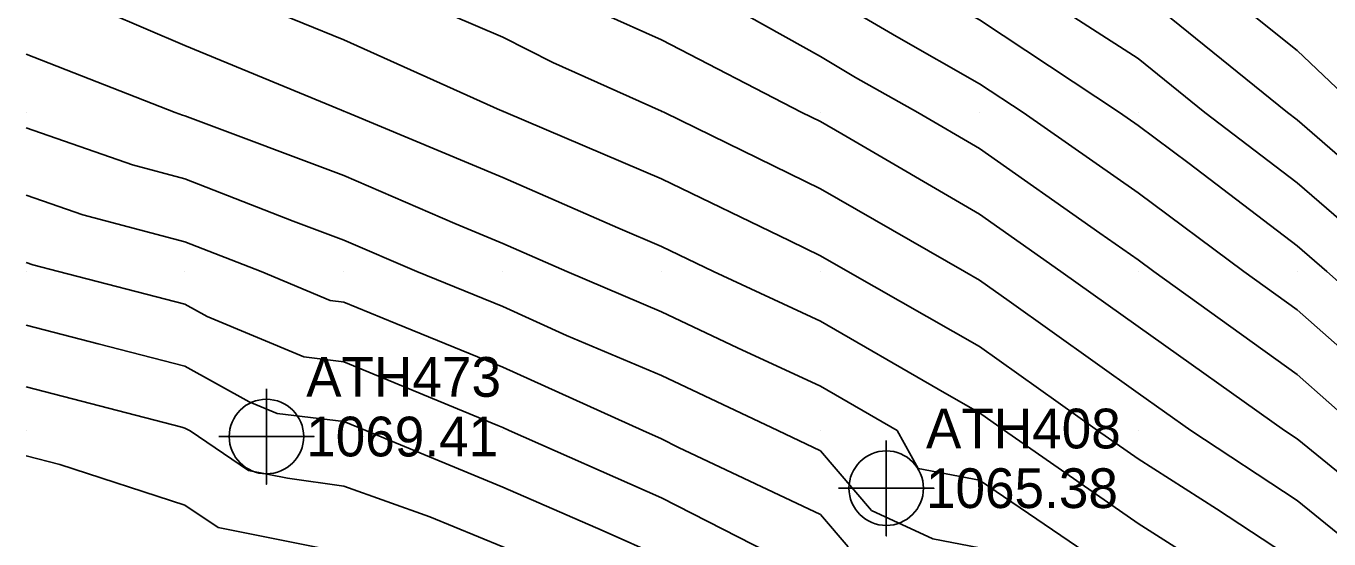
# Model space of a CAD drawing. Extents: x 1213164 to 1213550, y 766120 to 766870.
# Drawn here: x 1213170 to 1213252, y 766303.2 to 766335.4 of the extents above; entities that cross this region are included whole.
import ezdxf

# ---------------------------------------------------------------- set-up
doc = ezdxf.new("R2010")
doc.units = 0
for name, color, linetype in [('Default', 7, 'Continuous'), ('Exist DTM QL2 LIDAR Elevation Point', 7, 'Continuous'), ('Exist DTM Regular Point CELL', 7, 'Continuous'), ('Exist DTM Regular Point Cogo Elevation', 7, 'Continuous'), ('Exist DTM Regular Point Cogo Number', 7, 'Continuous')]:
    doc.layers.add(name, color=color, linetype=linetype)

msp = doc.modelspace()

# ---------------------------------------------------------------- linework, layer by layer
at = {"layer": 'Default'}
for points in [[(1213254.11, 766330), (1213250, 766333.906), (1213242.397, 766340), (1213240, 766341.58), (1213235.649, 766344.351), (1213230, 766347.761), (1213225.936, 766350), (1213220, 766353.174), (1213213.578, 766356.422), (1213210, 766358.269), (1213208.856, 766358.856), (1213206.616, 766360), (1213200, 766363.217), (1213193.598, 766366.402), (1213190, 766368.183), (1213182.11, 766370), (1213180, 766370.389), (1213179.565, 766370.435), (1213170, 766371.892)], [(1213280, 766300.545), (1213270.63, 766310), (1213270, 766310.688), (1213260.995, 766320), (1213260, 766320.923), (1213253.326, 766326.674), (1213250, 766329.544), (1213249.402, 766330), (1213240, 766337.619), (1213236.293, 766340), (1213230, 766343.799), (1213221.541, 766348.459), (1213220, 766349.323), (1213218.726, 766350), (1213210, 766354.505), (1213206.367, 766356.367), (1213200, 766359.619), (1213199.265, 766360), (1213190, 766364.587), (1213184.041, 766365.959), (1213180, 766367.027), (1213171.308, 766368.692), (1213170, 766368.959)], [(1213276.631, 766300), (1213270, 766306.688), (1213266.673, 766310), (1213260, 766316.88), (1213256.467, 766320), (1213250, 766325.581), (1213244.199, 766330), (1213240, 766333.403), (1213230.486, 766339.514), (1213230, 766339.835), (1213229.895, 766339.895), (1213229.716, 766340), (1213220, 766345.451), (1213211.434, 766350), (1213210, 766350.74), (1213203.878, 766353.878), (1213200, 766355.859), (1213191.999, 766360), (1213190, 766360.99), (1213188.714, 766361.286), (1213180, 766363.589), (1213175.561, 766364.439), (1213170, 766365.577)], [(1213270, 766302.77), (1213262.739, 766310), (1213260, 766312.824), (1213251.874, 766320), (1213250, 766321.617), (1213243.209, 766326.791), (1213240, 766329.186), (1213238.829, 766330), (1213230, 766335.826), (1213227.335, 766337.335), (1213222.813, 766340), (1213220, 766341.578), (1213216.634, 766343.366), (1213210, 766346.896), (1213204.099, 766350), (1213201.389, 766351.389), (1213200, 766352.098), (1213195.651, 766354.349), (1213190, 766356.816), (1213180.571, 766360), (1213180, 766360.151), (1213179.813, 766360.187), (1213170, 766362.194)], [(1213268.891, 766300), (1213260, 766308.854), (1213258.598, 766310), (1213250, 766317.59), (1213246.649, 766320), (1213240, 766324.962), (1213232.752, 766330), (1213230, 766331.816), (1213224.775, 766334.775), (1213220, 766337.59), (1213215.698, 766340), (1213210, 766343.032), (1213203.604, 766346.396), (1213200, 766348.087), (1213195.55, 766350), (1213190, 766352.422), (1213186.342, 766353.658), (1213180, 766356.001), (1213171.968, 766358.032), (1213170, 766358.69)], [(1213265.104, 766300), (1213260, 766305.082), (1213253.986, 766310), (1213250, 766313.518), (1213240.988, 766320), (1213240, 766320.738), (1213237.58, 766322.42), (1213230, 766327.738), (1213226.127, 766330), (1213222.215, 766332.215), (1213220, 766333.521), (1213211.993, 766338.007), (1213210, 766339.037), (1213209.334, 766339.334), (1213208.013, 766340), (1213200, 766343.759), (1213193.406, 766346.594), (1213190, 766347.998), (1213184.923, 766350), (1213180, 766351.819), (1213177.565, 766352.435), (1213170, 766354.961)], [(1213260, 766301.311), (1213252.811, 766307.189), (1213250, 766309.475), (1213249.199, 766310), (1213240, 766316.542), (1213235.135, 766320), (1213230, 766323.602), (1213221.338, 766328.662), (1213220, 766329.432), (1213218.836, 766330), (1213210, 766334.564), (1213206.242, 766336.242), (1213200, 766339.388), (1213198.575, 766340), (1213190, 766343.534), (1213184.165, 766345.835), (1213180, 766347.509), (1213173.693, 766350), (1213170, 766351.233)], [(1213256.902, 766300), (1213250, 766305.613), (1213243.308, 766310), (1213240, 766312.352), (1213231.867, 766318.133), (1213230, 766319.462), (1213229.055, 766320), (1213220, 766325.211), (1213210.178, 766330), (1213210, 766330.092), (1213203.15, 766333.15), (1213200, 766334.738), (1213191.698, 766338.302), (1213190, 766339.065), (1213187.713, 766340), (1213180, 766343.099), (1213174.877, 766345.123), (1213170, 766347.129)], [(1213250, 766301.751), (1213244.916, 766305.084), (1213240, 766308.217), (1213237.431, 766310), (1213230, 766315.291), (1213221.721, 766320), (1213220, 766320.99), (1213218.068, 766321.932), (1213210, 766325.834), (1213200.188, 766330), (1213200.058, 766330.058), (1213200, 766330.087), (1213199.847, 766330.153), (1213190, 766334.579), (1213182.255, 766337.745), (1213180, 766338.678), (1213176.902, 766340), (1213170, 766342.839)], [(1213246.514, 766300), (1213240, 766304.152), (1213231.573, 766310), (1213230, 766311.12), (1213227.402, 766312.598), (1213220, 766316.876), (1213213.267, 766320), (1213210, 766321.58), (1213207.254, 766322.746), (1213200, 766325.921), (1213190.206, 766330), (1213190, 766330.092), (1213189.844, 766330.156), (1213180, 766334.227), (1213172.625, 766337.375), (1213170, 766338.401)], [(1213239.716, 766300.284), (1213230, 766306.889), (1213226.146, 766307.619), (1213224.835, 766310), (1213220, 766312.795), (1213214.786, 766315.214), (1213210, 766317.474), (1213204.028, 766320), (1213200, 766321.763), (1213196.979, 766323.021), (1213190, 766326.033), (1213180.326, 766329.674), (1213180, 766329.801), (1213179.842, 766329.842), (1213179.392, 766330), (1213170, 766333.67)], [(1213230, 766302.636), (1213227.067, 766303.191), (1213223.222, 766304.966), (1213220, 766308.734), (1213217.318, 766310), (1213210, 766313.457), (1213204.01, 766315.99), (1213200, 766317.806), (1213194.593, 766320), (1213190, 766321.982), (1213186.822, 766323.178), (1213180, 766325.836), (1213176.703, 766326.703), (1213170, 766329.05)], [(1213221.741, 766302.684), (1213220, 766304.721), (1213211.062, 766308.938), (1213210, 766309.482), (1213208.825, 766310), (1213200, 766313.997), (1213193.273, 766316.727), (1213190, 766318.082), (1213189.148, 766318.184), (1213184.802, 766320), (1213180, 766321.87), (1213173.564, 766323.564), (1213170, 766324.812)], [(1213218.661, 766301.339), (1213210, 766305.771), (1213200.416, 766310), (1213200, 766310.189), (1213199.683, 766310.317), (1213190, 766314.326), (1213187.478, 766314.628), (1213181.4, 766317.168), (1213180, 766317.942), (1213172.04, 766320), (1213170.425, 766320.425), (1213170, 766320.574)], [(1213246.98, 766280), (1213240, 766284.817), (1213231.271, 766290), (1213230, 766290.761), (1213228.077, 766291.923), (1213220, 766296.782), (1213214.026, 766300), (1213210, 766302.06), (1213206.313, 766303.687), (1213200, 766306.436), (1213191.376, 766310), (1213190, 766310.569), (1213185.809, 766311.072), (1213184.051, 766311.807), (1213180, 766314.048), (1213174.541, 766315.459), (1213170, 766316.634)], [(1213241.401, 766280), (1213240, 766280.967), (1213237.62, 766282.38), (1213230, 766287.014), (1213224.78, 766290), (1213220, 766292.875), (1213213.767, 766296.233), (1213210, 766298.257), (1213206.168, 766300), (1213200, 766302.686), (1213195.422, 766304.578), (1213190, 766306.512), (1213186.456, 766307.003), (1213183.996, 766307.498), (1213180.319, 766309.977), (1213180, 766310.153), (1213179.794, 766310.206), (1213170, 766312.742)], [(1213235.427, 766280), (1213230, 766283.3), (1213222.29, 766287.71), (1213220, 766288.989), (1213218.075, 766290), (1213210, 766294.338), (1213202.04, 766297.96), (1213200, 766298.861), (1213196.73, 766300), (1213190, 766302.401), (1213188.693, 766302.582), (1213182.084, 766303.91), (1213180, 766305.315), (1213172.134, 766307.866), (1213170, 766308.402)]]:
    msp.add_lwpolyline(points, dxfattribs=at)
at = {"layer": 'Exist DTM QL2 LIDAR Elevation Point'}
for p, q in [((1213170, 766330), (1213170, 766330)), ((1213180, 766330), (1213180, 766330)), ((1213190, 766330), (1213190, 766330)), ((1213200, 766330), (1213200, 766330)), ((1213210, 766330), (1213210, 766330)), ((1213220, 766330), (1213220, 766330)), ((1213230, 766330), (1213230, 766330)), ((1213240, 766330), (1213240, 766330)), ((1213250, 766330), (1213250, 766330)), ((1213170, 766320), (1213170, 766320)), ((1213180, 766320), (1213180, 766320)), ((1213190, 766320), (1213190, 766320)), ((1213200, 766320), (1213200, 766320)), ((1213210, 766320), (1213210, 766320)), ((1213220, 766320), (1213220, 766320)), ((1213230, 766320), (1213230, 766320)), ((1213240, 766320), (1213240, 766320)), ((1213250, 766320), (1213250, 766320)), ((1213170, 766310), (1213170, 766310)), ((1213180, 766310), (1213180, 766310)), ((1213190, 766310), (1213190, 766310)), ((1213200, 766310), (1213200, 766310)), ((1213210, 766310), (1213210, 766310)), ((1213220, 766310), (1213220, 766310)), ((1213230, 766310), (1213230, 766310)), ((1213240, 766310), (1213240, 766310)), ((1213250, 766310), (1213250, 766310))]:
    msp.add_line(p, q, dxfattribs=at)
at = {"layer": 'Exist DTM Regular Point CELL'}
for points in [[(1213185.13, 766312.625), (1213185.13, 766306.625), (1213185.13, 766309.625), (1213188.13, 766309.625), (1213182.13, 766309.625)], [(1213224.138, 766309.378), (1213224.138, 766303.378), (1213224.138, 766306.378), (1213227.138, 766306.378), (1213221.138, 766306.378)]]:
    msp.add_lwpolyline(points, dxfattribs=at)
for centre in [(1213185.13, 766309.625), (1213224.138, 766306.378)]:
    msp.add_circle(centre, 2.344, dxfattribs=at)

# ---------------------------------------------------------------- texts
at = {"layer": 'Exist DTM Regular Point Cogo Elevation'}
for s, p in [('1069.41', (1213187.63, 766308.375)), ('1065.38', (1213226.638, 766305.128))]:
    msp.add_text(s, height=2.5, dxfattribs=at).set_placement(p)
at = {"layer": 'Exist DTM Regular Point Cogo Number'}
for s, p in [('ATH473', (1213187.63, 766312.125)), ('ATH408', (1213226.638, 766308.878))]:
    msp.add_text(s, height=2.5, dxfattribs=at).set_placement(p)

doc.saveas('drawing.dxf')
